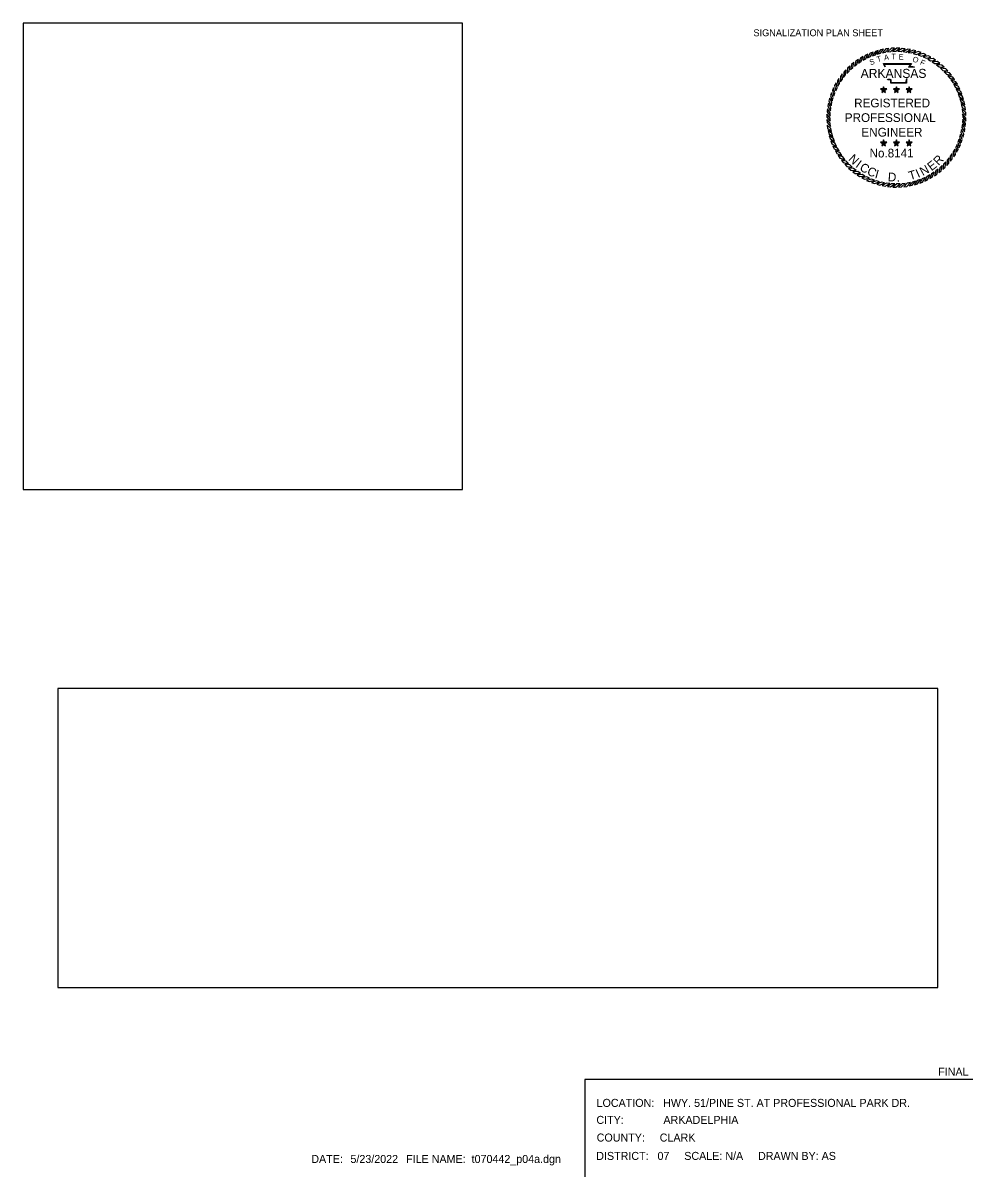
# Model space of a CAD drawing. Extents: x 418532 to 419834, y -565899 to -565285.
# Drawn here: x 419336 to 419834, y -565899 to -565293 of the extents above; entities that cross this region are included whole.
import ezdxf

# ---------------------------------------------------------------- set-up
doc = ezdxf.new("R2010")
doc.units = 0
for name, color, linetype in [('G-ANNO-SYMB', 7, 'Continuous'), ('G-ANNO-TEXT', 7, 'Continuous'), ('Level 10', 7, 'Continuous'), ('Level 57', 7, 'Continuous'), ('No Plot', 7, 'Continuous'), ('V-SIGNAL-LOOP', 7, 'Continuous')]:
    doc.layers.add(name, color=color, linetype=linetype)

msp = doc.modelspace()

# ---------------------------------------------------------------- linework, layer by layer
at = {"layer": 'G-ANNO-SYMB'}
for points in [[(419781.74, -565308.57), (419780.28, -565309.13), (419778.9, -565311.56), (419780.45, -565310.86)], [(419784.48, -565307.71), (419782.97, -565308.16), (419781.41, -565310.47), (419783, -565309.9)], [(419787.27, -565307.08), (419785.73, -565307.4), (419783.99, -565309.59), (419785.63, -565309.14)], [(419790.1, -565306.66), (419788.55, -565306.86), (419786.64, -565308.9), (419788.31, -565308.59)], [(419792.96, -565306.46), (419791.39, -565306.54), (419789.33, -565308.43), (419791.02, -565308.24)], [(419795.82, -565306.49), (419794.26, -565306.45), (419792.05, -565308.17), (419793.75, -565308.12)], [(419798.68, -565306.75), (419797.12, -565306.58), (419794.79, -565308.12), (419796.48, -565308.2)], [(419801.5, -565307.23), (419799.96, -565306.94), (419797.51, -565308.29), (419799.2, -565308.51)], [(419804.28, -565307.93), (419802.76, -565307.52), (419800.22, -565308.68), (419801.88, -565309.02)], [(419806.99, -565308.84), (419805.52, -565308.31), (419802.89, -565309.27), (419804.52, -565309.74)], [(419771.73, -565314.04), (419770.51, -565315.02), (419769.95, -565317.76), (419771.2, -565316.62)], [(419774.06, -565312.38), (419772.77, -565313.27), (419772, -565315.95), (419773.34, -565314.91)], [(419776.52, -565310.91), (419775.16, -565311.69), (419774.18, -565314.31), (419775.6, -565313.38)], [(419779.09, -565309.64), (419777.67, -565310.31), (419776.49, -565312.84), (419777.97, -565312.03)], [(419809.63, -565309.96), (419808.2, -565309.32), (419805.5, -565310.07), (419807.09, -565310.67)], [(419812.16, -565311.29), (419810.79, -565310.54), (419808.04, -565311.07), (419809.58, -565311.79)], [(419814.59, -565312.81), (419813.28, -565311.96), (419810.5, -565312.27), (419811.97, -565313.11)], [(419816.89, -565314.52), (419815.65, -565313.56), (419812.85, -565313.66), (419814.26, -565314.61)], [(419765.6, -565320.04), (419764.64, -565321.28), (419764.74, -565324.07), (419765.69, -565322.67)], [(419767.48, -565317.88), (419766.43, -565319.04), (419766.31, -565321.84), (419767.37, -565320.51)], [(419769.53, -565315.88), (419768.39, -565316.95), (419768.05, -565319.73), (419769.21, -565318.49)], [(419819.05, -565316.4), (419817.88, -565315.35), (419815.09, -565315.23), (419816.41, -565316.29)], [(419821.05, -565318.45), (419819.97, -565317.31), (419817.2, -565316.97), (419818.43, -565318.13)], [(419822.89, -565320.65), (419821.9, -565319.43), (419819.16, -565318.87), (419820.3, -565320.12)], [(419824.55, -565322.98), (419823.66, -565321.69), (419820.97, -565320.92), (419822.01, -565322.26)], [(419762.37, -565324.76), (419761.62, -565326.14), (419762.15, -565328.88), (419762.87, -565327.35)], [(419763.89, -565322.34), (419763.04, -565323.65), (419763.35, -565326.43), (419764.19, -565324.96)], [(419787.33, -565328.4), (419787.71, -565327.88), (419787.33, -565326.73), (419786.96, -565327.88)], [(419794, -565328.4), (419794.38, -565327.88), (419794, -565326.73), (419793.63, -565327.88)], [(419800.67, -565328.4), (419801.05, -565327.88), (419800.67, -565326.73), (419800.3, -565327.88)], [(419826.02, -565325.44), (419825.24, -565324.08), (419822.62, -565323.1), (419823.55, -565324.52)], [(419827.29, -565328.01), (419826.62, -565326.59), (419824.08, -565325.41), (419824.9, -565326.89)], [(419759.01, -565332.65), (419758.6, -565334.16), (419759.76, -565336.71), (419760.1, -565335.05)], [(419759.92, -565329.93), (419759.39, -565331.41), (419760.35, -565334.04), (419760.82, -565332.41)], [(419761.04, -565327.3), (419760.4, -565328.73), (419761.15, -565331.43), (419761.75, -565329.84)], [(419787.33, -565328.4), (419786.96, -565327.88), (419785.75, -565327.88), (419786.73, -565328.6)], [(419787.33, -565328.4), (419786.73, -565328.6), (419786.35, -565329.75), (419787.33, -565329.04)], [(419787.33, -565328.4), (419787.94, -565328.6), (419788.92, -565327.88), (419787.71, -565327.88)], [(419787.33, -565328.4), (419787.33, -565329.04), (419788.31, -565329.75), (419787.94, -565328.6)], [(419794, -565328.4), (419793.63, -565327.88), (419792.42, -565327.88), (419793.4, -565328.6)], [(419794, -565328.4), (419793.4, -565328.6), (419793.02, -565329.75), (419794, -565329.04)], [(419794, -565328.4), (419794.61, -565328.6), (419795.59, -565327.88), (419794.38, -565327.88)], [(419794, -565328.4), (419794, -565329.04), (419794.98, -565329.75), (419794.61, -565328.6)], [(419800.67, -565328.4), (419800.3, -565327.88), (419799.09, -565327.88), (419800.07, -565328.6)], [(419800.67, -565328.4), (419800.07, -565328.6), (419799.69, -565329.75), (419800.67, -565329.04)], [(419800.67, -565328.4), (419801.28, -565328.6), (419802.26, -565327.88), (419801.05, -565327.88)], [(419800.67, -565328.4), (419800.67, -565329.04), (419801.65, -565329.75), (419801.28, -565328.6)], [(419828.36, -565330.67), (419827.8, -565329.2), (419825.36, -565327.82), (419826.06, -565329.37)], [(419829.21, -565333.4), (419828.77, -565331.89), (419826.45, -565330.33), (419827.03, -565331.92)], [(419829.85, -565336.19), (419829.53, -565334.66), (419827.34, -565332.91), (419827.79, -565334.55)], [(419757.83, -565338.25), (419757.66, -565339.81), (419759.2, -565342.14), (419759.28, -565340.45)], [(419758.31, -565335.43), (419758.02, -565336.97), (419759.37, -565339.41), (419759.58, -565337.73)], [(419830.27, -565339.02), (419830.07, -565337.47), (419828.02, -565335.56), (419828.34, -565337.23)], [(419830.46, -565341.88), (419830.38, -565340.31), (419828.5, -565338.25), (419828.68, -565339.94)], [(419757.57, -565341.1), (419757.53, -565342.67), (419759.25, -565344.87), (419759.2, -565343.18)], [(419757.54, -565343.97), (419757.62, -565345.53), (419759.51, -565347.59), (419759.32, -565345.91)], [(419830.18, -565347.6), (419830.35, -565346.04), (419828.8, -565343.71), (419828.72, -565345.4)], [(419830.43, -565344.74), (419830.48, -565343.18), (419828.76, -565340.97), (419828.81, -565342.67)], [(419757.74, -565346.82), (419757.94, -565348.38), (419759.98, -565350.29), (419759.66, -565348.62)], [(419758.15, -565349.66), (419758.48, -565351.19), (419760.67, -565352.93), (419760.22, -565351.3)], [(419829, -565353.2), (419829.41, -565351.68), (419828.25, -565349.14), (419827.91, -565350.8)], [(419829.7, -565350.42), (419829.99, -565348.88), (419828.63, -565346.43), (419828.42, -565348.12)], [(419758.79, -565352.45), (419759.24, -565353.95), (419761.55, -565355.52), (419760.98, -565353.92)], [(419759.65, -565355.18), (419760.21, -565356.65), (419762.64, -565358.02), (419761.94, -565356.48)], [(419787.33, -565356.33), (419786.96, -565355.81), (419785.75, -565355.81), (419786.73, -565356.53)], [(419787.33, -565356.33), (419786.73, -565356.53), (419786.35, -565357.68), (419787.33, -565356.97)], [(419787.33, -565356.33), (419787.71, -565355.81), (419787.33, -565354.66), (419786.96, -565355.81)], [(419787.33, -565356.33), (419787.94, -565356.53), (419788.92, -565355.81), (419787.71, -565355.81)], [(419787.33, -565356.33), (419787.33, -565356.97), (419788.31, -565357.68), (419787.94, -565356.53)], [(419794, -565356.33), (419793.63, -565355.81), (419792.42, -565355.81), (419793.4, -565356.53)], [(419794, -565356.33), (419793.4, -565356.53), (419793.02, -565357.68), (419794, -565356.97)], [(419794, -565356.33), (419794.38, -565355.81), (419794, -565354.66), (419793.63, -565355.81)], [(419794, -565356.33), (419794.61, -565356.53), (419795.59, -565355.81), (419794.38, -565355.81)], [(419794, -565356.33), (419794, -565356.97), (419794.98, -565357.68), (419794.61, -565356.53)], [(419800.67, -565356.33), (419800.3, -565355.81), (419799.09, -565355.81), (419800.07, -565356.53)], [(419800.67, -565356.33), (419800.07, -565356.53), (419799.69, -565357.68), (419800.67, -565356.97)], [(419800.67, -565356.33), (419801.05, -565355.81), (419800.67, -565354.66), (419800.3, -565355.81)], [(419800.67, -565356.33), (419801.28, -565356.53), (419802.26, -565355.81), (419801.05, -565355.81)], [(419800.67, -565356.33), (419800.67, -565356.97), (419801.65, -565357.68), (419801.28, -565356.53)], [(419825.64, -565361.09), (419826.39, -565359.71), (419825.85, -565356.96), (419825.13, -565358.5)], [(419826.96, -565358.55), (419827.6, -565357.12), (419826.86, -565354.42), (419826.26, -565356.01)], [(419828.09, -565355.91), (419828.61, -565354.44), (419827.66, -565351.81), (419827.19, -565353.44)], [(419760.72, -565357.84), (419761.39, -565359.26), (419763.92, -565360.44), (419763.11, -565358.95)], [(419761.99, -565360.4), (419762.77, -565361.77), (419765.39, -565362.74), (419764.46, -565361.33)], [(419763.46, -565362.86), (419764.35, -565364.16), (419767.03, -565364.93), (419765.99, -565363.59)], [(419822.4, -565365.81), (419823.36, -565364.57), (419823.26, -565361.77), (419822.31, -565363.18)], [(419824.11, -565363.51), (419824.97, -565362.2), (419824.65, -565359.42), (419823.81, -565360.89)], [(419765.12, -565365.2), (419766.1, -565366.42), (419768.84, -565366.98), (419767.7, -565365.72)], [(419766.96, -565367.4), (419768.03, -565368.54), (419770.81, -565368.88), (419769.57, -565367.72)], [(419816.28, -565371.81), (419817.5, -565370.82), (419818.06, -565368.08), (419816.8, -565369.22)], [(419818.47, -565369.97), (419819.62, -565368.89), (419819.96, -565366.12), (419818.8, -565367.35)], [(419820.52, -565367.97), (419821.57, -565366.8), (419821.7, -565364.01), (419820.64, -565365.33)], [(419768.96, -565369.44), (419770.12, -565370.49), (419772.92, -565370.62), (419771.59, -565369.56)], [(419771.12, -565371.33), (419772.36, -565372.28), (419775.15, -565372.19), (419773.75, -565371.23)], [(419773.42, -565373.03), (419774.73, -565373.89), (419777.51, -565373.57), (419776.03, -565372.73)], [(419775.84, -565374.56), (419777.22, -565375.31), (419779.96, -565374.77), (419778.43, -565374.05)], [(419778.38, -565375.88), (419779.81, -565376.52), (419782.5, -565375.78), (419780.92, -565375.18)], [(419803.53, -565378.13), (419805.03, -565377.69), (419806.6, -565375.37), (419805, -565375.95)], [(419806.26, -565377.28), (419807.73, -565376.72), (419809.1, -565374.29), (419807.56, -565374.98)], [(419808.92, -565376.21), (419810.34, -565375.54), (419811.52, -565373), (419810.03, -565373.82)], [(419811.48, -565374.94), (419812.84, -565374.16), (419813.82, -565371.54), (419812.41, -565372.47)], [(419813.94, -565373.47), (419815.24, -565372.58), (419816.01, -565369.89), (419814.67, -565370.93)], [(419781.01, -565377.01), (419782.49, -565377.53), (419785.12, -565376.58), (419783.49, -565376.11)], [(419783.73, -565377.92), (419785.24, -565378.33), (419787.79, -565377.17), (419786.13, -565376.83)], [(419786.51, -565378.62), (419788.05, -565378.91), (419790.49, -565377.55), (419788.81, -565377.34)], [(419789.33, -565379.1), (419790.89, -565379.27), (419793.22, -565377.72), (419791.53, -565377.64)], [(419792.18, -565379.35), (419793.75, -565379.4), (419795.95, -565377.68), (419794.26, -565377.73)], [(419795.05, -565379.38), (419796.61, -565379.31), (419798.67, -565377.42), (419796.99, -565377.6)], [(419797.9, -565379.19), (419799.46, -565378.99), (419801.37, -565376.94), (419799.7, -565377.26)], [(419800.74, -565378.77), (419802.27, -565378.45), (419804.01, -565376.26), (419802.38, -565376.71)]]:
    msp.add_lwpolyline(points, close=True, dxfattribs=at)
for points in [[(419788.16, -565316.45), (419787.31, -565314.61), (419802.02, -565314.6), (419800.79, -565316.14), (419801.79, -565316.13), (419802.63, -565316.12), (419803.46, -565316.21)], [(419788.37, -565316.35), (419787.67, -565314.84), (419801.54, -565314.83), (419800.3, -565316.38), (419801.79, -565316.36), (419802.62, -565316.35), (419803.44, -565316.44)], [(419799.7, -565322.62), (419799.45, -565322.82), (419799.37, -565323.13), (419799.29, -565323.89), (419799.29, -565324.9), (419791.07, -565324.9), (419791.07, -565323.53), (419791.07, -565323.23), (419790.74, -565323.13), (419789.57, -565323.13), (419789.36, -565322.81)], [(419799.56, -565322.43), (419799.25, -565322.69), (419799.14, -565323.08), (419799.05, -565323.88), (419799.05, -565324.67), (419791.31, -565324.67), (419791.31, -565323.53), (419791.31, -565323.05), (419790.77, -565322.89), (419789.7, -565322.89), (419789.56, -565322.68)]]:
    msp.add_lwpolyline(points, dxfattribs=at)
at = {"layer": 'Level 57'}
for points in [[(419630.59, -565847.55), (419630.59, -565898.75)], [(419834.17, -565847.55), (419630.59, -565847.55)]]:
    msp.add_lwpolyline(points, dxfattribs=at)
at = {"layer": 'No Plot'}
msp.add_lwpolyline([(419353.98, -565799.37), (419815.79, -565799.37), (419815.79, -565642.42), (419353.98, -565642.42)], close=True, dxfattribs=at)
at = {"layer": 'V-SIGNAL-LOOP'}
msp.add_lwpolyline([(419335.72, -565538.11), (419566.27, -565538.11), (419566.27, -565293.32), (419335.72, -565293.32)], close=True, dxfattribs=at)

# ---------------------------------------------------------------- texts
at = {"layer": 'G-ANNO-SYMB'}
for s, height, rotation, p in [('S', 2.9, 19.77256, (419780.5, -565315.49)), ('T', 2.9, 16.90148, (419784.19, -565313.83)), ('A', 2.9, 8.67877, (419787.71, -565312.91)), ('T', 2.9, 1.47887, (419791.46, -565312.33)), ('E', 2.9, 356.67203, (419795.17, -565312.42)), ('O', 2.9, 341.2218, (419802.22, -565313.41)), ('F', 2.9, 335.36282, (419806.13, -565314.94)), ('N', 4.59, 315.26758, (419768.52, -565364.92)), ('R', 4.59, 45.47796, (419816.09, -565368.32)), ('I', 4.59, 324.21406, (419772.25, -565368.62)), ('C', 4.59, 328.68731, (419774.32, -565370.23)), ('C', 4.59, 336.51548, (419778.23, -565372.66)), ('N', 4.59, 28.7033, (419807.82, -565373.62)), ('E', 4.59, 37.64979, (419812.43, -565371.1)), ('I', 4.59, 344.34365, (419782.42, -565374.53)), ('D', 4.59, 356.64507, (419789.42, -565376.27)), ('T', 4.59, 16.77466, (419801.18, -565375.81)), ('I', 4.59, 24.23006, (419805.39, -565374.6)), ('.', 4.59, 4.84601, (419794.23, -565376.59))]:
    msp.add_text(s, height=height, rotation=rotation, dxfattribs=at).set_placement(p)
for s, height, p in [('ARKANSAS', 4.737, (419775.28, -565322.09)), ('REGISTERED', 4.585, (419771.84, -565337.55)), ('PROFESSIONAL', 4.5855, (419766.93, -565345.22)), ('ENGINEER', 4.585, (419775.66, -565352.88)), ('No.8141', 4.567, (419779.94, -565363.82))]:
    msp.add_text(s, height=height, dxfattribs=at).set_placement(p)
at = {"layer": 'G-ANNO-TEXT'}
msp.add_text('SIGNALIZATION PLAN SHEET', height=3.6, dxfattribs=at).set_placement((419718.99, -565300.21))
at = {"layer": 'Level 10'}
for s, p in [('FINAL', (419815.96, -565845.65)), ('LOCATION:   HWY. 51/PINE ST. AT PROFESSIONAL PARK DR.', (419636.68, -565862.01)), ('CITY:', (419636.6, -565870.93)), (' ARKADELPHIA', (419670.2, -565870.93)), ('COUNTY:     CLARK', (419636.75, -565880.2)), ('DATE:  ', (419486.98, -565891.43)), ('5/23/2022', (419507.52, -565891.43)), ('  FILE NAME: ', (419533.62, -565891.43)), ('t070442_p04a.dgn', (419571.11, -565891.43)), ('DISTRICT:   07     SCALE: N/A     DRAWN BY: AS', (419636.51, -565889.83))]:
    msp.add_text(s, height=4.2, rotation=360, dxfattribs=at).set_placement(p)

doc.saveas('drawing.dxf')
